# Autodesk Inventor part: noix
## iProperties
Shininess: 20.0
Length Units: 11269
Angle Units: 11279
Time Units: 11290
Mass Units: 11283
Length Display Precision: 3
Angle Display Precision: 2
Compacted: True
Created: 2002-07
Part Number: noix
Material: Par défaut
Document SubType Name: Modélisation
Designer: robert
Density: 1 g/cm^3
Density: 0.0
Volumn: 0.0
Area: 0.0
PropertySet Name: Model Information
Control State: 0
Master: False
Checked Out: False
Author: robert
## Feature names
1. Extrusion1
